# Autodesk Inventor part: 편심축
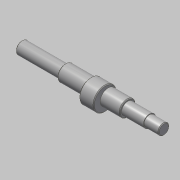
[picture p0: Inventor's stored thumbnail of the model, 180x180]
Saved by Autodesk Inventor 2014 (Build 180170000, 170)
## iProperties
Created: 2016-05
Part Number: 편심축
Document SubType Name: Modeling
Designer: mduedu
Density: 7.86 g/cm^3
Material: 강철, 연강
Appearance: 강철
Author: mduedu
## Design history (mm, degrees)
sketch "스케치1"
  geometry: L1 (-38, 11)-(-38, 8.5); L2 (48, 11)-(48, 8.5); L3 (-98, 0)-(98, 0); L4 (-38, 11)-(48, 11); L5 (48, 11)-(48, 8.5); L6 (-38, 11)-(-38, 8.5); L7 (-38, 8.5)-(-98, 8.5); L8 (-98, 8.5)-(-98, 0); L9 (48, 8.5)-(78, 8.5); L10 (98, 7.5)-(98, 0); L11 (78, 8.5)-(78, 7.5); L12 (78, 7.5)-(98, 7.5); 1 further point
  constraints: 24 end point, 9 perpendicular, 2 midpoint, 1 collinear, 1 horizontal
  dimensions: "d0" = 22 diameter of L4 L3; "d1" = 17 diameter of L7 L3; "d2" = 60 distance between parallel lines of L8 L1; "d3" = 50 distance between parallel lines of L10 L2; "d4" = 15 diameter of L12 L3; "d5" = 20 distance between parallel lines of L10 L11; "d29" = 86 distance of L1.start L2.start
revolve "회전1" stored, may be unused: angle "d6" = 90 deg
node "작업 평면7"
node "작업 평면9"
sketch "스케치2"
  geometry: C1 r 11 at (0, 0); C2 r 16 at (0, -4); C3 r 11 at (0, 0); 2 further points
  constraints: 3 centre point, 2 coincident, 1 concentric, 1 vertical alignment
  dimensions: "d9" = 4 distance of point (0, 0) C2.centre; "d10" = 32 diameter of C2
extrude "돌출1" join sketch "스케치2" stored distance "d11" = 20; taper "d12" = 0 deg
chamfer "모따기1" distance "d17" = 1; stored, may be unused: second distance "d18" = 2, angle "d19" = 45 deg
node "작업 평면4"
sketch "스케치4"
  geometry: L1 (-10, -6.5)-(-10, 6.5) reference; L2 (-5, 2.5)-(5, 2.5); L3 (5, -2.5)-(-5, -2.5); A1 r 2.5 centre (5, 0) between (5, -2.5) and (5, 2.5); A2 r 2.5 centre (-5, 0) between (-5, 2.5) and (-5, -2.5); 2 further points
  constraints: 4 end point, 4 point on circle, 4 tangent, 2 centre point, 1 horizontal alignment, 1 midpoint, 1 parallel, 1 perpendicular
  dimensions: "d20" = 5 distance between parallel lines of L3 L2; "d21" = 15 dimension on A1 A2; "d22" = 2.5 distance edge to line of A2 L1
extrude "돌출3" cut sketch "스케치4" distance "d23" = 3; taper "d24" = 0 deg
node "작업 평면5"
sketch "스케치5"
  geometry: L1 (30, 7.5)-(30, -7.5) reference; L2 (30, 2.5)-(12.5, 2.5); L3 (12.5, -2.5)-(30, -2.5); A1 r 2.5 centre (12.5, 0) between (12.5, 2.5) and (12.5, -2.5); 2 further points
  constraints: 4 end point, 2 perpendicular, 2 point on circle, 2 point on line, 2 tangent, 1 centre point, 1 horizontal alignment, 1 midpoint
  dimensions: "d25" = 5 distance between parallel lines of L3 L2; "d26" = 20 dimension on A1 L1
extrude "돌출4" cut sketch "스케치5" distance "d27" = 3; taper "d28" = 0 deg
node "솔리드1"
other parameters: "d31" = -37
